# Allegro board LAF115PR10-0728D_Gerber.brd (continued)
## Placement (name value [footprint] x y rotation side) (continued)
PRS23  100K_0402_5%  [R_0402]  51.24 119.59 90 top
PRS25  1M_0402_1%  [R_0402]  57.31 128.38 90 top
PRS26  1M_0402_1%  [R_0402]  65.72 120.83 90 top
PRS27  1M_0402_1%  [R_0402]  65.75 123.43 270 top
PRS28  10K_0402_1%  [R_0402]  62.32 122.56 90 top
PRS29  100K_0402_1%  [R_0402]  64.94 124.26 0 top
PRS30  100K_0402_1%  [R_0402]  64.25 116.98 180 top
PRS32  0_0402_5%  [R_0402]  45.7 117.91 180 top
PRS33  0_0402_5%  [R_0402]  52.07 122.84 270 top
PRS34  10K_0402_1%  [R_0402]  62.26 124.44 90 top
PRS35  0_0402_5%  [R_0402]  66.39 127.14 270 top
PRS36  300K_0402_1%  [R_0402]  53.95 135.07 270 top
PRS37  100K_0402_5%  [R_0402]  52.82 131 180 top
PRS38  0_0402_5%  [R_0402]  49.48 127.71 0 top
PRS39  0_0402_5%  [R_0402]  48.15 118.82 0 top
PRS40  0_0402_5%  [R_0402]  49.81 118.82 0 top
PRS41  0_0402_5%  [R_0402]  52.84 122.84 270 top
PRS42  0_0402_5%  [R_0402]  51.24 122.97 90 top
PRS43  0_0402_5%  [R_0402]  53.64 124.28 180 top
PRS44  0_0402_5%  [R_0402]  54.44 124.28 0 top
PRS45  0_0402_5%  [R_0402]  41.72 125.97 90 top
PRV01  0_0603_5%  [R0603_0OHM]  77.12 133.79 0 top
PRV02  32.4K_0402_1%  [R_0402]  73.19 133.73 90 top
PRV03  10K_0402_1%  [R_0402]  67.22 120.79 0 top
PRV04  10K_0402_1%  [R_0402]  73.96 133.73 90 top
PRV05  10K_0402_1%  [R_0402]  74.74 133.73 90 top
PRV06  4.7_1206_5%  [R_1206]  90.92 134.44 270 top
PRV07  3.65K_0603_1%  [R_0603]  66.96 121.79 0 top
PRV08  1_0402_1%  [R_0402]  66.89 123.71 270 top
PRV09  100K_0402_1%  [R_0402]  69.95 132.33 180 top
PRV10  100K_0402_1%  [R_0402]  71.79 133.71 90 top
PRV12  0_0402_5%  [R_0402]  67.84 131.06 0 top
PRV13  1_0603_5%  [R_0603]  79.6 131.06 270 top
PRV14  0_0402_5%  [R_0402]  67.84 130.23 0 top
PRV15  0_0402_5%  [R0402_0OHM]  68.73 129.34 0 top
PRV16  133K_0402_1%  [R_0402]  67.98 128.53 270 top
PRV17  100K_0402_1%  [R_0402]  79.49 125.85 180 top
PRV18  150K_0402_1%  [R_0402]  67.15 125.71 90 top
PRV19  13.3K_0402_1%  [R_0402]  67.98 126.63 270 top
PRV20  0_0402_5%  [R0402_0OHM]  78.59 125.05 0 top
PRV21  0_0603_5%  [R0603_0OHM]  78.39 127.25 0 top
PRV22  10K_0402_1%  [R_0402]  70.25 120.25 270 top
PRV23  4.7_1206_5%  [R_1206]  90.97 125.45 90 top
PRV24  3.65K_0603_1%  [R_0603]  68.08 118.46 90 top
PRV25  1_0402_1%  [R_0402]  71.92 121.84 90 top
PRV26  301_0402_1%  [R_0402]  73.76 124.53 270 top
PRV27  121K_0402_1%  [R_0402]  77.05 122.61 0 top
PRV28  2.61K_0402_1%  [R_0402]  70.9 122.03 270 top
PRV29  1.37K_0402_1%  [R_0402]  74.58 124.53 270 top
PRV30  11K_0402_1%  [R_0402]  70.07 123.49 90 top
PRV31  22.1K_0402_1%  [R_0402]  74.52 121.99 270 top
PRV32  2K_0402_1%  [R_0402]  73.69 121.99 270 top
PRV33  665_0402_1%  [R_0402]  72.68 123.62 90 top
PRV34  0_0402_5%  [R0402_0OHM]  76.31 123.57 180 top
PRV35  100_0402_1%  [R_0402]  71.85 123.62 90 top
PRV36  0_0402_5%  [R0402_0OHM]  77.57 124.44 90 top
PRW01  0_0402_5%  [R0402_0OHM]  140.06 112.25 270 bottom
PRW02  1M_0402_1%  [R_0402]  139.28 111.34 90 bottom
PRW03  0_0402_5%  [R_0402]  147.39 111.15 180 top
PRW04  0_0402_5%  [R_0402]  145.14 111.45 90 bottom
PRW05  100K_0402_5%  [R_0402]  140.88 112.25 270 bottom
PRW06  10_0603_5%  [R_0603]  144.81 108.13 0 top
PRW07  4.7_1206_5%  [R_1206]  147.78 109.77 0 top
PRW09  39.2K_0402_1%  [R_0402]  143.46 111.49 90 bottom
PRW10  31.6K_0402_1%  [R_0402]  142.67 112.24 180 bottom
PRW11  2.2_0402_1%  [R_0402]  144.82 110.75 225 top
PRW13  1K_0402_1%  [R_0402]  146.04 114.4 225 bottom
PRZ01  1.5K_0402_1%  [R_0402]  182.16 55.82 90 top
PRZ03  0_0402_5%  [R0402_0OHM]  182.36 53.61 180 top
PRZ04  1.78K_0402_1%  [R_0402]  181.21 52.72 180 bottom
PRZ05  18.2K_0402_1%  [R_0402]  179.02 55.4 180 top
PRZ06  10_0402_5%  [R_0402]  183.14 56.17 180 bottom
PRZ07  0_0402_5%  [R0402_0OHM]  182.36 54.5 180 top
PRZ08  1K_0402_1%  [R_0402]  181.26 54.47 180 bottom
PRZ10  12K_0402_1%  [R_0402]  180.7 59.08 270 top
PRZ11  20K_0402_1%  [R_0402]  178.11 54.52 0 top
PRZ13  7.5K_0603_1%  [R_0603]  154.03 58.95 270 top
PRZ14  0_0402_5%  [R0402_0OHM]  182.15 51.71 180 bottom
PRZ15  54.9K_0402_1%  [R_0402]  179.02 57.13 180 top
PRZ16  10K_0402_1%  [R_0402]  180.76 58.52 180 bottom
PRZ18  0_0402_5%  [R0402_0OHM]  181.26 50.02 90 bottom
PRZ19  1K_0402_1%  [R_0402]  180.38 51.5 90 top
PRZ20  49.9_0402_1%  [R_0402]  179.57 49.56 270 bottom
PRZ21  619_0402_1%  [R_0402]  179.58 50.44 180 bottom
PRZ22  0_0402_5%  [R0402_0OHM]  179.84 59.3 0 bottom
PRZ23  24.9K_0402_1%  [R_0402]  177.45 52.32 90 top
PRZ24  4.75K_0402_1%  [R_0402]  178.5 50.22 270 top
PRZ25  66.5K_0603_1%  [R_0603]  176.33 48.98 90 top
PRZ26  165K_0402_1%  [R_0402]  174.87 48.68 0 bottom
PRZ27  75K_0402_1%  [R_0402]  176.52 48.68 0 bottom
PRZ28  9.76K_0402_1%  [R_0402]  177.17 49.56 90 bottom
PRZ29  66.5K_0603_1%  [R_0603]  175.12 48.98 90 top
PRZ30  10_0402_1%  [R_0402]  159.79 72.77 0 bottom
PRZ31  10_0402_1%  [R_0402]  160.99 71.64 0 bottom
PRZ32  10K_0402_1%  [R_0402]  173.69 49.64 180 top
PRZ33  10K_0402_1%  [R_0402]  174.39 49.57 180 bottom
PRZ34  0_0402_5%  [R0402_0OHM]  171.79 52.02 0 top
PRZ35  1K_0402_1%  [R_0402]  170.68 50.52 0 bottom
PRZ36  61.9K_0402_1%  [R_0402]  171.79 52.91 0 top
PRZ37  2.15K_0402_1%  [R_0402]  171.96 47.34 90 top
PRZ38  2.15K_0402_1%  [R_0402]  173.61 47.34 90 top
PRZ39  1K_0402_1%  [R_0402]  172.79 47.34 90 top
PRZ40  45.3_0402_1%  [R_0402]  178.06 61.12 90 top
PRZ41  110_0402_1%  [R_0402]  177.17 61.12 90 top
PRZ42  100_0402_1%  [R_0402]  176.28 61.12 90 top
PRZ43  110_0402_1%  [R_0402]  175.39 61.12 90 top
PRZ44  7.5K_0603_1%  [R_0603]  152.56 94.61 90 top
PRZ45  12K_0402_1%  [R_0402]  174.27 63.04 270 bottom
PRZ46  49.9_0402_1%  [R_0402]  177.49 60.7 90 bottom
PRZ47  0_0402_5%  [R0402_0OHM]  176.71 61.13 90 bottom
PRZ48  10_0402_1%  [R_0402]  175.92 61.13 90 bottom
PRZ49  100_0402_1%  [R_0402]  175.15 61.13 90 bottom
PRZ50  97.6K_0402_1%  [R_0402]  176.47 59.41 270 top
PRZ51  10_0402_5%  [R_0402]  173.5 63.03 270 bottom
PRZ52  1K_0402_1%  [R_0402]  169.27 58.93 90 bottom
PRZ53  0_0402_5%  [R0402_0OHM]  171.39 62.03 90 top
PRZ55  2K_0402_1%  [R_0402]  171.81 63.04 270 bottom
PRZ56  52.3K_0402_1%  [R_0402]  173.89 59.41 270 top
PRZ57  2_0402_1%  [R_0402]  169.32 51.96 0 bottom
PRZ58  4.32K_0402_1%  [R_0402]  169.8 60.76 270 top
PRZ59  0_0402_5%  [R0402_0OHM]  169.8 62.92 270 top
PRZ60  24K_0402_1%  [R_0402]  171.79 53.8 0 top
PRZ61  3.65K_0402_1%  [R_0402]  168.98 60.76 270 top
PRZ63  0_0402_5%  [R0402_0OHM]  170.18 57.14 270 bottom
PRZ64  24K_0402_1%  [R_0402]  170.16 54.12 180 bottom
PRZ65  61.9K_0402_1%  [R_0402]  169.29 56.23 90 bottom
PRZ66  51.1K_0402_1%  [R_0402]  171.79 54.69 0 top
PRZ67  97.6K_0402_1%  [R_0402]  171.79 55.58 0 top
PRZ68  19.1K_0402_1%  [R_0402]  171.79 56.47 0 top
PRZ69  35.7K_0402_1%  [R_0402]  171.79 57.36 0 top
PU1  -  [RT9069-33GB_SOT23-5]  83.84 144.17 180 top
PU2  -  [SN74AHC1G08DCKR_SC70-5]  95.96 147.73 90 top
PU301  -  [SY8286BRAC_QFN20_3X3]  20.79 41.49 90 bottom
PU501  SY8180CRAC_QFN20_3X3  [SY8288CRAC_QFN20_3X3]  24.66 98.72 270 bottom
PU1801  -  [RT8061AZQW_WDFN10_3X3]  167.06 43.42 90 bottom
PU2501  -  [RT9059GSP_SO8]  71.51 110.42 90 top
PUA01  -  [NCP81253MNTBG_DFN8_2X2]  166.06 59.69 270 bottom
PUB01  -  [ISL9538HRTZ-T_TQFN32_4X4]  205.97 43.79 90 bottom
PUB02  SN74AHC1G08DCKR_SC70-5  [TC7SH08FU_SSOP5]  165.07 34.08 270 top
PUG01  -  [NCP302045MNTXG_PQFN33_5X5]  157.84 95.25 0 bottom
PUH01  -  [RT6228AGQUF_UQFN12_3X3]  162.56 49.8 90 bottom
PUI01  -  [NCP302045MNTXG_PQFN33_5X5]  162.02 70.01 0 bottom
PUI02  -  [NCP302045MNTXG_PQFN33_5X5]  166.87 87.52 270 bottom
PUM01  -  [RT8207PGQW_WQFN20_3X3]  37.65 30.36 180 top
PUS01  AS393MMTR-G1_MSOP8  [LM393DGKR_VSSOP8]  48.98 115.91 0 top
PUS02  -  [SN74AHC1G08DCKR_SC70-5]  59.69 125.79 90 top
PUS03  -  [TC7SH32FU_SSOP5]  52.17 126.54 270 top
PUS04  RT9058-33GX SOT-89 3P  [AP2204R-5P0TRG1_SOT89-3]  77.28 144.12 0 top
PUV01  -  [ISL62771HRTZ-T_TQFN40_5X5]  71.63 131.5 0 top
PUW01  -  [RT6226AGQUF_UQFN12_3X3]  144.7 109.12 180 bottom
PUZ01  -  [NCP81218MNTXG_QFN48_6X6]  177.63 52.85 90 bottom
Q1  -  [2N7002K_SOT23-3]  44.04 52.46 180 top
Q4  -  [L2N7002WT1G_SC-70-3]  59.98 33.43 270 top
Q6  -  [LN2306LT1G_SOT23-3]  46.38 48.11 270 top
Q7  -  [DDTA144VCA-7-F_SOT23-3]  48.1 44.11 90 top
Q8  -  [LN2306LT1G_SOT23-3]  82.16 47.8 270 top
Q9  -  [LN2306LT1G_SOT23-3]  124.58 26.06 0 top
Q10  -  [DMN66D0LDW-7_SOT363-6]  119.04 28.44 270 top
Q11  -  [DMN66D0LDW-7_SOT363-6]  182.26 65.13 0 top
Q12  NTK3139PT1G_SOT723-3  [2N7002K_SOT23-3]  131.29 27.39 0 top
Q13  -  [2N7002K_SOT23-3]  135.29 29.36 180 top
Q14  -  [LMBT3904LT1G_SOT23-3]  84.83 118.42 270 bottom
Q15  LP2301ALT1G 1P SOT-23-3  [SI2301CDS-T1-GE3_SOT23-3]  60.24 27.21 0 top
Q17  -  [DMN66D0LDW-7_SOT363-6]  46.61 95.85 90 top
Q18  -  [DDTA144VCA-7-F_SOT23-3]  48.36 94.47 270 top
Q19  -  [DDTA144VCA-7-F_SOT23-3]  48.36 98.47 270 top
Q20  -  [DDTA144VCA-7-F_SOT23-3]  50.81 37.07 180 top
Q21  -  [LN2306LT1G_SOT23-3]  55.48 32.09 0 top
Q22  -  [LN2306LT1G_SOT23-3]  48.3 102.4 270 top
Q23  -  [LP2301ALT1G_SOT23-3]  64.22 30.25 180 top
Q24  -  [L2N7002WT1G_SC-70-3]  65.95 32.21 180 top
Q25  -  [DMN66D0LDW-7_SOT363-6]  51.65 107.2 0 top
QA1  -  [LN2306LT1G_SOT23-3]  36.7 20.39 180 top
QC1  -  [DMN66D0LDW-7_SOT363-6]  100.09 36.74 0 bottom
QC2  -  [2N7002K_SOT23-3]  99 45.23 0 top
QI1  -  [2N7002K_SOT23-3]  27.54 92.85 90 top
QI2  -  [DMN66D0LDW-7_SOT363-6]  26.04 88.04 90 bottom
QI3  2N7002KW_SOT323-3  [DMN65D8LW-7_SOT323-3]  26.36 114.07 90 top
QS1  -  [DMN66D0LDW-7_SOT363-6]  195.93 37.05 180 top
QT3  -  [2N7002K_SOT23-3]  21.06 130.79 270 top
QT4  -  [LN2306LT1G_SOT23-3]  26.46 117.77 270 top
QT5  -  [LN2306LT1G_SOT23-3]  33.28 130.51 270 top
QV1  DMN66D0LDW-7 2N SOT363-6  [2N7002KDWH_SOT363-6]  123.66 120.85 0 top
R1  1K_0402_5%  [R_0402]  41.82 48.08 270 top
R2  10M_0402_5%  [R_0402]  42.64 47.77 90 top
R3  0_0805_5%  [R_0805]  212.35 50.33 270 top
R4  0_0603_5%  [R_0603]  217.17 25.25 90 top
R5  10K_0402_5%  [R_0402]  210.05 55.35 270 top
R6  0_0402_5%  [R_0402]  210.05 53.7 270 top
R7  0_0603_5%  [R_0603]  216.03 29.06 270 top
R8  0_0402_5%  [R0402_0OHM]  178.3 70.9 45 top
R9  0_0402_5%  [R_0402]  177.73 71.47 45 top
R10  100K_0402_5%  [R_0402]  166.61 31.81 180 top
R11  0_0603_5%  [R_0603]  215.58 33.76 90 top
R12  0_0603_5%  [R_0603]  216.92 37.57 180 bottom
R13  0_0603_5%  [R_0603]  213.39 40.08 180 top
R16  0_0603_5%  [R_0603]  212.33 47.6 270 top
R17  0_0402_5%  [R_0402-NPM]  214.33 43.86 0 top
R18  0_0402_5%  [R_0402-NPM]  214.33 44.62 0 top
R19  33_0402_5%  [R_0402]  214.09 41.43 90 top
R20  0_0402_5%  [R_0402]  207.98 39.98 0 top
R21  0_0402_5%  [R_0402]  207.98 40.75 0 top
R22  100_0402_5%  [R_0402]  219.92 66.95 270 top
R23  10K_0402_5%  [R_0402]  55.51 81.77 180 top
R24  100K_0402_5%  [R_0402]  50.15 47.45 90 top
R25  1K_0402_5%  [R_0402]  50.17 44.76 90 top
R26  51K_0402_5%  [R_0402]  88.16 35.99 0 bottom
R27  100K_0402_5%  [R_0402]  87.38 35.95 90 bottom
R28  18.7K_0402_1%  [R_0402]  174.96 64.4 315 bottom
R29  2K_0402_1%  [R_0402]  178.43 61.14 315 bottom
R30  10K_0402_5%  [R_0402]  208.61 37 180 top
R31  4.7K_0402_5%  [R_0402]  115.88 27.57 180 top
R32  4.7K_0402_5%  [R_0402]  118.09 26.12 270 top
R33  4.7K_0402_5%  [R_0402]  121.95 27.61 270 top
R34  4.7K_0402_5%  [R_0402]  118.57 30.05 45 top
R35  0_0402_5%  [R_0402]  128.99 31.28 0 top
R36  0_0603_5%  [R_0603]  129.78 25.4 0 top
R37  100_0603_5%  [R_0603]  135.29 25.38 180 top
R38  20K_0402_1%  [R_0402]  133.37 31.25 180 top
R39  10K_0402_5%  [R_0402]  122.21 25.07 90 top
R40  4.7K_0402_5%  [R_0402]  127.91 26.67 270 top
R41  100K_0402_5%  [R_0402]  117.98 33.36 0 bottom
R42  24.9K_0402_1%  [R_0402]  109.5 107.62 90 top
R43  7.15K_0402_1%  [R_0402]  111.3 107.71 90 top
R45  0_0402_5%  [R_0402]  122.94 43.21 90 top
R46  2.2K_0402_5%  [R_0402]  121.95 29.24 270 top
R47  2.2K_0402_5%  [R_0402]  116.99 26.96 90 top
R48  2.2K_0402_5%  [R_0402]  183.05 64.11 180 top
R49  2.2K_0402_5%  [R_0402]  182.77 68.05 0 top
R50  10K_0402_5%  [R_0402]  180.37 69.4 45 top
R53  100K_0402_5%  [R_0402]  53.17 35.75 270 top
R57  10K_0402_5%  [R_0402]  209.71 50.05 180 top
R65  499K_0402_1%  [R_0402]  61.03 31.54 0 top
R66  100K_0402_5%  [R_0402]  59.67 31.55 180 top
R67  49.9K_0402_1%  [R_0402]  61.95 32.43 180 top
R68  200_0402_5%  [R_0402]  16.18 131.61 0 bottom
R69  200_0402_5%  [R_0402]  16.18 132.38 0 bottom
R70  100K_0402_5%  [R_0402]  219.11 66.05 90 top
R71  0_0402_5%  [R_0402]  43.79 95.55 90 top
R72  100K_0402_5%  [R_0402]  223.13 33.61 180 bottom
R73  10K_0402_5%  [R_0402]  64.25 34.35 270 top
R77  0_0402_5%  [R_0402]  39.9 24.27 0 bottom
R78  1M_0402_5%  [R_0402]  69 30.74 270 top
R79  100K_0402_5%  [R_0402]  67.51 28.29 180 top
R80  0_0402_5%  [R_0402]  214.65 47.71 0 top
R81  0_0402_5%  [R_0402]  49.46 104.75 0 top
R82  100K_0402_5%  [R_0402]  53.13 110.17 180 top
R83  100K_0402_5%  [R_0402]  53.97 110.17 270 top
R84  0_0402_5%  [R_0402]  62.63 26.32 0 top
R85  0_0603_5%  [R_0603]  215.58 48.8 180 top
R86  0_0402_5%  [R_0402]  219.12 27.34 270 top
R87  0_0402_5%  [R_0402]  220.07 26.42 90 top
RA1  0_0805_5%  [R0805_0OHM]  31.8 3.23 180 top
RA2  0_0402_5%  [R0402_0OHM]  33.71 21.2 180 top
RA3  100K_0402_5%  [R_0402]  31.1 17.86 0 top
RA4  0_0603_5%  [R0603_0OHM]  31.82 19.06 180 top
RA5  0_0402_5%  [R0402_0OHM]  22.04 6.7 90 top
RA6  0_0402_5%  [R0402_0OHM]  21.28 6.05 180 top
RA7  33_0402_5%  [R_0402]  32.57 14.79 180 top
RA8  10K_0402_5%  [R_0402]  30.88 8.04 180 top
RA9  0_0402_5%  [R_0402]  38.53 15.47 0 top
RA10  200K_0402_1%  [R_0402]  30.37 17.86 180 top
RA11  0_0402_5%  [R_0402]  29.22 22.06 0 top
RA12  0_0402_5%  [R_0402]  29.22 22.84 0 top
RA13  BLM15PD800SN1D_2P  [MURAT_BLM15PD600SN1D_2P]  26.79 3.92 180 top
RA14  BLM15PD800SN1D_2P  [MURAT_BLM15PD600SN1D_2P]  26.79 2.77 180 top
RA15  BLM15PD800SN1D_2P  [MURAT_BLM15PD600SN1D_2P]  26.2 7.65 270 top
RA16  BLM15PD800SN1D_2P  [MURAT_BLM15PD600SN1D_2P]  27.34 7.65 270 top
RA17  0_0402_5%  [R0402_0OHM]  12.76 6.1 270 top
RA18  0_0402_5%  [R0402_0OHM]  11.97 6.1 270 top
RA22  0_0805_5%  [R0805_0OHM]  24.83 23.59 90 top
RA23  1K_0402_5%  [R_0402]  30.13 21.28 180 top
RA24  10K_0402_5%  [R_0402]  29.21 20.51 0 top
RA25  2.2K_0402_5%  [R_0402]  27.75 19.64 180 top
RA26  2.2K_0402_5%  [R_0402]  25.21 18.85 0 top
RA27  10_0402_1%  [R_0402]  20.35 12.67 180 top
RA28  1K_0402_5%  [R_0402]  21.84 19.96 90 top
RA29  4.7K_0402_5%  [R_0402]  20.35 13.44 180 top
RA30  10K_0402_5%  [R_0402]  16.38 11.46 90 bottom
RA31  10_0402_1%  [R_0402]  16.34 12.3 90 top
RA32  1K_0402_5%  [R_0402]  22.61 19.96 90 top
RA33  4.7K_0402_5%  [R_0402]  18.89 14.46 180 top
RA34  10K_0402_5%  [R_0402]  16.38 14.15 270 bottom
RA35  BLM15PX330SN1D_2P  [MURAT_BLM15PX330SN1D_2P]  26.93 20.74 90 top
RA36  0_0402_5%  [R0402_0OHM]  18.72 12.15 180 top
RA37  0_0402_5%  [R0402_0OHM]  17.26 14 180 top
RA38  BLM15PX330SN1D_2P  [MURAT_BLM15PX330SN1D_2P]  26.02 20.74 90 top
RA39  0_0603_5%  [R0603_0OHM]  16.72 19.27 270 top
RA40  0_0402_5%  [R0402_0OHM]  15.71 18.17 90 top
RA41  100K_0402_5%  [R_0402]  19.47 17.74 270 top
RA42  33_0402_5%  [R_0402]  32.62 10.35 180 top
RA43  33_0402_5%  [R_0402]  34.49 15.41 180 top
RC1  2.2K_0402_5%  [R_0402]  131.89 39.54 270 bottom
RC2  2.2K_0402_5%  [R_0402]  131.09 39.52 270 bottom
RC3  10K_0402_5%  [R_0402]  141.19 48.4 270 bottom
RC4  24.9_0402_1%  [R_0402]  144.28 82.51 270 top
RC5  100K_0402_5%  [R_0402]  128.86 52.23 90 top
RC6  100K_0402_5%  [R_0402]  128.56 54.87 90 top
RC7  100_0402_1%  [R_0402]  133.99 55.98 180 top
RC8  200_0402_1%  [R_0402]  115.72 46.26 270 bottom
RC9  100K_0402_5%  [R_0402]  105.48 104.04 270 top
RC10  121_0402_1%  [R_0402]  104.21 60.49 180 top
RC11  80.6_0402_1%  [R_0402]  105.09 62.21 225 top
RC12  100_0402_1%  [R_0402]  106.19 60.49 180 top
RC14  10K_0402_5%  [R_0402]  104.52 51.94 0 top
RC15  22_0402_5%  [R_0402]  106.19 54.97 180 top
RC17  0_0603_5%  [R0603_0OHM]  130.37 40.49 180 bottom
RC18  4.7K_0402_5%  [R_0402]  114.94 45.34 90 bottom
RC19  1K_0402_5%  [R_0402]  110.42 45.27 90 bottom
RC20  1K_0402_5%  [R_0402]  114.05 46.26 270 bottom
RC21  33_0402_5%  [R_0402]  109.53 45.62 90 bottom
RC22  1M_0402_1%  [R_0402]  144.4 45.33 270 bottom
RC23  33_0402_5%  [R_0402]  141.99 73.24 90 bottom
RC24  33_0402_5%  [R_0402]  141.99 71.47 90 bottom
RC25  33_0402_5%  [R_0402]  142.75 44.53 0 bottom
RC26  33_0402_5%  [R_0402]  142.75 45.29 0 bottom
RC27  2.2K_0402_5%  [R_0402]  100.35 33.89 0 bottom
RC28  2.2K_0402_5%  [R_0402]  103.63 37.55 180 bottom
RC29  1K_0402_5%  [R_0402]  128.83 41.51 0 bottom
RC30  1K_0402_5%  [R_0402]  128.83 42.4 0 bottom
RC31  1K_0402_5%  [R_0402]  130.91 46.4 270 bottom
RC32  1K_0402_5%  [R_0402]  131.73 46.46 270 bottom
RC33  1K_0402_5%  [R_0402]  127.54 53.96 270 top
RC34  1K_0402_5%  [R_0402]  129.26 46.4 270 bottom
RC35  10K_0402_5%  [R_0402]  144.34 39.25 180 bottom
RC36  10K_0402_5%  [R_0402]  123.43 44.43 0 bottom
RC37  2.2K_0402_5%  [R_0402]  127.49 57 0 top
RC38  4.7K_0402_5%  [R_0402]  130.09 46.4 270 bottom
RC39  150K_0402_5%  [R_0402]  121.29 46.07 180 top
RC40  1K_0402_1%  [R_0402]  106.17 39.21 90 bottom
RC41  1K_0402_1%  [R_0402]  113.03 45.8 180 bottom
RC42  10K_0402_5%  [R_0402]  125.49 45.55 90 bottom
RC44  4.7K_0402_5%  [R_0402]  110.82 51.71 90 bottom
RC45  10K_0402_5%  [R_0402]  122.22 46.07 0 top
RC46  10K_0402_5%  [R_0402]  131.96 42.2 180 bottom
RC47  10K_0402_5%  [R_0402]  122.3 46.41 270 bottom
RC48  10K_0402_5%  [R_0402]  143.04 37.42 270 bottom
RC49  10K_0402_5%  [R_0402]  143.97 38.27 180 bottom
RC50  150K_0402_5%  [R_0402]  143.93 36.5 90 bottom
RC51  10K_0402_5%  [R_0402]  123.43 42.78 0 bottom
RC52  10K_0402_5%  [R_0402]  124.35 43.6 180 bottom
RC53  10K_0402_5%  [R_0402]  120.65 45.5 90 bottom
RC54  10K_0402_5%  [R_0402]  122.18 42.7 90 bottom
RC55  10K_0402_5%  [R_0402]  126.25 45.55 90 bottom
RC56  10K_0402_5%  [R_0402]  127.03 46.47 270 bottom
RC57  10K_0402_5%  [R_0402]  125.59 44.63 270 bottom
RC58  10K_0402_5%  [R_0402]  126.48 43.71 90 bottom
RC59  10K_0402_5%  [R_0402]  104.57 41.38 0 top
RC60  10K_0402_5%  [R_0402]  105.36 40.55 180 top
RC61  10K_0402_5%  [R_0402]  129.74 43.22 180 bottom
RC62  10K_0402_5%  [R_0402]  128.83 44.05 0 bottom
RC63  10K_0402_5%  [R_0402]  145.81 47.98 180 bottom
RC64  10K_0402_5%  [R_0402]  144.9 48.75 0 bottom
RC65  100_0402_1%  [R_0402]  133.08 52.41 0 top
RC66  113_0402_1%  [R_0402]  126.4 51.95 270 top
RC67  1K_0402_5%  [R_0402]  122.23 50.58 90 top
RC68  1K_0402_5%  [R_0402]  121.48 46.41 270 bottom
RC69  10K_0402_5%  [R_0402]  143.52 40.06 0 bottom
RC71  10K_0402_5%  [R_0402]  104.5 52.74 0 top
RC72  10K_0402_5%  [R_0402]  105.27 46.74 0 top
RC73  10K_0402_5%  [R_0402]  105.27 45.97 0 top
RC74  0_0402_5%  [R_0402]  100.78 39.21 90 bottom
RC75  0_0402_5%  [R_0402]  101.54 39.21 90 bottom
RC76  2.71K_0402_1%  [R_0402]  142.88 76.8 90 bottom
RC77  20K_0402_5%  [R_0402]  99.93 43.44 270 top
RC78  20K_0402_5%  [R_0402]  100.75 43.44 270 top
RC80  1M_0402_1%  [R_0402]  142.88 73.24 90 bottom
RC82  10M_0402_5%  [R_0402]  104.28 50.23 0 top
RC86  10K_0402_5%  [R_0402]  139.78 48 90 bottom
RC87  100K_0402_5%  [R_0402]  98.45 40.12 270 bottom
RC88  10K_0402_5%  [R_0402]  105.36 39.75 180 top
RC89  8.2K_0402_5%  [R_0402]  106.19 54.02 180 top
RC90  10K_0402_5%  [R_0402]  103.49 54.02 0 top
RC91  1M_0402_5%  [R_0402]  99.1 43.44 270 top
RC92  10K_0402_5%  [R_0402]  121.4 51.48 270 top
RC93  100K_0402_5%  [R_0402]  105.27 56.55 0 top
RC94  10K_0402_5%  [R_0402]  105.26 58.71 0 top
RC95  1K_0402_5%  [R_0402]  140.66 91.86 180 bottom
RC96  60.4_0402_1%  [R_0402]  140.66 87.16 180 bottom
RC97  0_0402_5%  [R0402_0OHM]  108.88 58.9 0 bottom
RC99  0_0402_5%  [R0402_0OHM]  105.27 55.73 0 top
RC102  1M_0402_5%  [R_0402]  100.63 28.43 180 bottom
RC103  10K_0402_1%  [R_0402]  147.02 87.93 180 bottom
RC104  1K_0402_5%  [R_0402]  142.22 87.79 0 bottom
RC105  10K_0402_5%  [R_0402]  148.35 91.86 180 bottom
RC106  0_0402_5%  [R0402_0OHM]  148.35 92.62 180 bottom
RC107  0_0402_5%  [R0402_0OHM]  147.44 93.45 0 bottom
RC108  0_0402_5%  [R_0402]  106.2 42.51 90 top
RC109  100K_0402_5%  [R_0402]  106.2 45.2 270 top
RC110  1K_0402_5%  [R_0402]  102.74 42.45 90 top
RC111  49.9_0402_1%  [R_0402]  143.26 84.24 180 bottom
RC112  1K_0402_5%  [R_0402]  143.26 85.13 180 bottom
RC113  1K_0402_5%  [R_0402]  128.65 96.38 270 top
RC114  10K_0402_5%  [R_0402]  109.53 49.7 0 bottom
RC115  10K_0402_5%  [R_0402]  108.75 49.73 270 bottom
RC116  10K_0402_5%  [R_0402]  141.46 51.28 0 bottom
RC117  499_0402_1%  [R_0402]  129.61 95.47 90 top
RC118  0_0402_5%  [R_0402]  109.53 48.87 0 bottom
RC119  49.9_0402_1%  [R_0402]  106.19 57.73 180 top
RC120  49.9_0402_1%  [R_0402]  104.21 59.6 180 top
RC121  49.9_0402_1%  [R_0402]  131.69 87.08 90 top
RC122  49.9_0402_1%  [R_0402]  131.69 86.22 270 top
RC123  33_0402_5%  [R_0402]  98.99 50.55 0 top
RC124  33_0402_5%  [R_0402]  108.5 60.39 0 bottom
RC125  33_0402_5%  [R_0402]  102.38 46.02 180 top
RC126  1K_0402_5%  [R_0402]  102.37 47.63 180 top
RC127  33_0402_5%  [R_0402]  101.57 50.54 180 top
RC128  8.2K_0402_5%  [R_0402]  103.56 46.59 0 top
RC129  4.7K_0402_5%  [R_0402]  102.37 46.84 180 top
RC130  200_0402_1%  [R_0402]  123.9 53.73 90 top
RC131  10K_0402_1%  [R_0402]  141.63 89.48 180 bottom
RC132  10K_0402_1%  [R_0402]  140.67 93.89 180 bottom
RC133  10K_0402_1%  [R_0402]  139.74 90.97 0 bottom
RC134  49.9_0402_1%  [R_0402]  133.49 83.98 180 top
RC136  10K_0402_1%  [R_0402]  133.53 91.08 90 top
RC137  0_0402_5%  [R_0402]  128.89 46.34 0 top
RC138  100K_0402_5%  [R_0402]  131.45 96.38 270 top
RC139  1K_0402_5%  [R_0402]  106.94 40.12 270 bottom
RC140  51_0402_5%  [R_0402]  127.76 95.47 90 top
RC141  51_0402_5%  [R_0402]  126.87 95.47 90 top
RC142  51_0402_5%  [R_0402]  125.99 95.47 90 top
RC143  1K_0402_5%  [R_0402]  129.16 50.45 90 top
RC144  0_0402_5%  [R_0402]  124.27 94.1 270 top
RC145  0_0402_5%  [R_0402]  105.7 37.4 180 top
RC146  51_0402_1%  [R_0402]  125.1 95.47 90 top
RC147  51_0402_5%  [R_0402]  139.81 83.33 0 bottom
RC148  1K_0402_5%  [R_0402]  99.21 40.12 270 bottom
RC149  0_0603_5%  [R_0603]  127.89 48.87 0 top
RC150  100_0402_1%  [R_0402]  141.83 67.1 90 bottom
RC151  100_0402_1%  [R_0402]  141.83 68.75 90 bottom
RC152  56_0402_1%  [R_0402]  143.26 86.02 180 bottom
RC153  220_0402_5%  [R_0402]  139.75 85.89 0 bottom
RC154  100_0402_1%  [R_0402]  143.13 86.9 180 bottom
RC155  100_0402_1%  [R_0402]  131.78 92.62 180 top
RC156  100_0402_1%  [R_0402]  130.56 92.81 90 bottom
RC157  0_0402_5%  [R_0402]  131.43 77.57 90 top
RC159  100_0402_1%  [R_0402]  146.59 57.54 90 top
RC160  100_0402_1%  [R_0402]  144.44 61.14 0 top
RC161  0_0603_5%  [R_0603]  145.86 45.25 270 top
RC162  0_0603_5%  [R_0603]  144.59 45.25 270 top
RC163  0_0402_5%  [R_0402]  102.95 39.59 180 top
RC164  10K_0402_5%  [R_0402]  96.58 47.04 90 top
RC169  0_0603_5%  [R0603_0OHM]  133.61 48.28 180 top
RC170  0_0603_5%  [R0603_0OHM]  144.54 55.03 270 top
RC171  0_0603_5%  [R0603_0OHM]  130.81 59.66 90 top
RC173  0_0603_5%  [R0603_0OHM]  126.68 60.68 0 top
RC174  0_0603_5%  [R0603_0OHM]  144.59 47.03 90 top
RC175  0_0402_5%  [R_0402]  124.27 96.38 270 top
RC176  15_0402_5%  [R_0402]  111.34 46.19 270 bottom
RC177  15_0402_5%  [R_0402]  121.27 37.82 0 bottom
RC178  15_0402_5%  [R_0402]  122.19 38.64 180 bottom
RC179  15_0402_5%  [R_0402]  122.18 39.43 180 bottom
RC180  15_0402_5%  [R_0402]  122.19 36.94 180 bottom
RC181  10K_0402_5%  [R_0402]  104.45 38.17 0 top
RC182  10K_0402_5%  [R_0402]  105.36 38.93 180 top
RC188  10K_0402_5%  [R_0402]  105.41 39.21 90 bottom
RC194  10K_0402_5%  [R_0402]  192.2 63.93 90 top
RC199  0_0402_5%  [R_0402]  100.05 40.86 180 top
RC200  10K_0402_5%  [R_0402]  128.8 43.39 0 top
RC201  0_0402_5%  [R_0402]  116.45 53.92 0 top
RC202  0_0402_5%  [R_0402]  113 95.36 180 bottom
RC203  0_0402_5%  [R_0402]  118.5 39.2 270 bottom
RC205  10K_0402_5%  [R_0402]  127.86 46.44 270 bottom
RC206  10K_0402_5%  [R_0402]  132.32 37.52 180 bottom
RC207  10K_0402_5%  [R_0402]  215.75 32.28 225 top
RC208  10K_0402_5%  [R_0402]  214.16 59.19 270 top
RC209  10K_0402_5%  [R_0402]  182.24 37.52 90 bottom
RC211  100K_0402_5%  [R_0402]  102.68 54.01 90 top
RC212  2.2K_0402_5%  [R_0402]  142.81 34.98 0 top
RC213  10K_0402_5%  [R_0402]  118.75 51.4 225 top
RC214  10K_0402_5%  [R_0402]  120.57 58.01 90 top
RC223  0_0402_5%  [R_0402]  42.63 90.08 180 top
RC224  10K_0402_5%  [R_0402]  47.53 100.95 270 top
RC225  10K_0402_5%  [R_0402]  44.2 101.02 180 top
RC226  10K_0402_5%  [R_0402]  42.82 98.53 180 top
RC227  1K_0402_5%  [R_0402]  130.36 25.48 90 bottom
RC442  0_0402_5%  [R_0402]  77.61 113.55 90 top
RD1  0_0402_5%  [R_0402]  70.16 42.64 90 top
RD2  0_0402_5%  [R_0402]  69.21 42.64 90 top
RD3  0_0402_5%  [R_0402]  68.11 67.16 0 top
RD4  0_0402_5%  [R0402_0OHM]  70.48 44.86 90 top
RD5  0_0402_5%  [R0402_0OHM]  69.4 44.99 135 top
RD6  0_0402_5%  [R0402_0OHM]  69.22 65.74 180 top
RD7  470_0402_1%  [R_0402]  70.92 82.02 90 top
RD8  0_0402_5%  [R0402_0OHM]  70.04 82.9 180 top
RD9  2_0402_1%  [R_0402]  70.78 64.62 0 top
RD10  1K_0402_1%~D  [R_0402]  70.78 67.48 0 top
RD11  24.9_0402_1%  [R_0402]  71.7 62.72 180 top
RD12  1K_0402_1%~D  [R_0402]  71.7 66.53 180 top
RD13  0_0402_5%  [R_0402]  55.41 44.24 0 top
RD14  0_0402_5%  [R0402_0OHM]  55.41 43.22 0 top
RD15  0_0402_5%  [R_0402]  56.25 68.7 270 top
RD16  0_0402_5%  [R0402_0OHM]  56.33 45.19 180 top
RD17  0_0402_5%  [R_0402]  56.33 42.27 180 top
RD18  0_0402_5%  [R0402_0OHM]  56.25 66.86 270 top
RD19  2_0402_1%  [R_0402]  58.07 68.05 0 top
RD20  1K_0402_1%~D  [R_0402]  58.07 67.1 0 top
RD21  1K_0402_1%~D  [R_0402]  58.97 66.13 180 top
RD22  24.9_0402_1%  [R_0402]  58.07 69.85 0 top
RD23  240_0402_1%  [R_0402]  71.96 76.62 180 top
RD24  240_0402_1%  [R_0402]  58.75 77.13 180 top
RE1  100K_0402_1%  [R_0402]  31.45 91.11 270 top
RE2  0_0603_5%  [R_0603]  43.08 60.66 90 top
RE3  100K_0402_1%  [R_0402]  30.95 87.24 270 top
RE4  100K_0402_1%  [R_0402]  31.75 87.23 270 top
RE6  100K_0402_1%  [R_0402]  35.76 91.11 180 top
RE7  0_0603_5%  [R0603_0OHM]  30.06 66.29 270 top
RE8  4.7K_0402_5%  [R_0402]  39.37 63.76 180 top
RE9  4.7K_0402_5%  [R_0402]  40.22 63.76 0 top
RE10  2.2K_0402_5%  [R_0402]  41.15 62.22 270 top
RE11  2.2K_0402_5%  [R_0402]  42.04 62.22 270 top
RE12  1K_0402_5%  [R_0402]  73.24 37.83 270 top
RE13  10K_0402_5%  [R_0402]  53.51 72.69 0 top
RE14  100K_0402_5%  [R_0402]  53.58 67.67 0 top
RE15  100K_0402_5%  [R_0402]  48.95 86.26 90 top
RE16  10K_0402_5%  [R_0402]  50.85 86.26 90 top
RE17  100K_0402_5%  [R_0402]  38.44 62.48 0 top
RE18  100K_0402_5%  [R_0402]  29.51 86.7 180 top
RE19  1K_0402_5%  [R_0402]  43.42 89.2 90 top
RE20  10K_0402_5%  [R_0402]  36.95 87.09 90 top
RE21  100K_0402_5%  [R_0402]  33.97 66.05 270 top
RE23  43_0402_1%  [R_0402]  34.92 87.09 90 top
RE25  100K_0402_5%  [R_0402]  52.58 87.11 270 top
RE28  0_0402_5%  [R0402_0OHM]  32.34 83.37 270 top
RE29  1K_0402_5%  [R_0402]  32.09 73.67 180 top
RE30  2.2K_0402_5%  [R_0402]  31.85 88.9 180 top
RE31  2.2K_0402_5%  [R_0402]  31.85 88.01 180 top
RE32  100K_0402_5%  [R_0402]  32.09 72.75 180 top
RE37  0_0402_5%  [R0402_0OHM]  38.81 88.81 180 top
RE41  100K_0402_5%  [R_0402]  31.4 66 0 top
RE42  0_0402_5%  [R0402_0OHM]  53.51 74.84 0 top
RE43  100_0402_5%  [R_0402]  32.32 65.21 180 top
RE45  0_0402_5%  [R_0402]  33.09 68.95 270 top
RE46  10K_0402_1%  [R_0402]  49.39 63.85 90 top
RE47  0_0402_5%  [R_0402]  33.09 70.73 270 top
RE48  10K_0402_1%  [R_0402]  48.49 64.76 270 top
RE49  100K_0402_5%  [R_0402]  38.79 88 270 top
RE50  0_0603_5%  [R0603_0OHM]  33.78 89.64 90 top
RE51  300_0402_5%  [R_0402]  32.02 78.13 270 top
RE52  100K_0402_5%  [R_0402]  37.9 88 270 top
RE53  100K_0402_5%  [R_0402]  37.19 89.66 90 top
RE54  300_0402_5%  [R_0402]  32.09 74.46 180 top
RE55  10K_0402_5%  [R_0402]  38.98 95.36 0 top
RE56  100K_0402_5%  [R_0402]  38.98 94.59 0 top
RE57  10K_0402_5%  [R_0402]  38.98 93.07 0 top
RE58  10K_0402_5%  [R_0402]  38.98 92.31 0 top
RE59  49.9_0402_1%  [R_0402]  45.63 91.52 90 top
RE60  0_0402_5%  [R0402_0OHM]  33.91 83.37 270 top
RE61  0_0402_5%  [R0402_0OHM]  40.32 87.24 270 top
RE62  10K_0402_5%  [R_0402]  39.89 93.83 180 top
RE63  0_0402_5%  [R0402_0OHM]  33.12 83.37 270 top
RE65  0_0402_5%  [R_0402]  44.52 99.65 270 top
RE66  0_0603_5%  [R0603_0OHM]  55.44 78.72 270 top
RE67  33_0402_5%  [R_0402]  54.87 79.71 180 top
RE68  10K_0402_5%  [R_0402]  50.26 64.76 270 top
RE70  100K_0402_5%  [R_0402]  32.32 66.78 180 top
RE71  2.2K_0402_5%  [R_0402]  53.57 66.84 0 top
RE72  0_0603_5%  [R_0603]  47.88 90.78 270 top
RE81  0_0402_5%  [R_0402]  52.09 64.78 270 top
RE84  0_0201_5%  [R_0201]  91.8 36.38 0 bottom
RE85  0_0402_5%  [R_0402]  53.44 88.27 270 top
RE88  0_0402_5%  [R_0402]  29.73 73.44 270 top
RE89  0_0402_5%  [R_0402]  28.94 73.44 270 top
RE90  0_0402_5%  [R_0402]  37.83 85.68 180 top
RE91  0_0402_5%  [R_0402]  38.57 85.68 0 top
RE539  1K_0402_5%  [R_0402]  41.72 89.2 0 top
RE540  0_0402_5%  [R_0402]  92.36 38.24 0 bottom
RE541  100K_0402_5%  [R_0402]  53.37 63.81 90 top
RH1  100K_0402_1%_B25/50 4250K  [R_0402]  124.63 44.17 180 top
RI1  5.6_0402_1%  [R_0402]  16.98 93.64 180 top
RI2  5.6_0402_1%  [R_0402]  16.98 94.66 180 top
RI3  150_0402_5%  [R_0402]  14.92 94.48 270 top
RI4  5.6_0402_1%  [R_0402]  16.98 96.69 180 top
RI5  5.6_0402_1%  [R_0402]  16.98 95.67 180 top
RI6  150_0402_5%  [R_0402]  14.92 96.57 270 top
RI7  5.6_0402_1%  [R_0402]  16.98 89.7 180 top
RI8  5.6_0402_1%  [R_0402]  16.98 90.72 180 top
RI9  150_0402_5%  [R_0402]  14.92 90.54 270 top
RI10  5.6_0402_1%  [R_0402]  16.98 91.67 180 top
RI11  5.6_0402_1%  [R_0402]  16.98 92.69 180 top
RI12  150_0402_5%  [R_0402]  14.92 92.64 270 top
RI13  2.2K_0402_5%  [R_0402]  26.84 90.72 180 bottom
RI14  2.2K_0402_5%  [R_0402]  23.81 89.09 90 bottom
RI15  1M_0402_5%  [R_0402]  29.35 113.39 90 top
RI16  20K_0402_5%  [R_0402]  13.9 110.29 90 bottom
RL1  0_0603_5%  [R_0603]  21.59 85.64 90 top
RL2  2.49K_0402_1%  [R_0402]  19.74 79.76 0 top
RL3  1K_0402_5%  [R_0402]  24.6 87.22 270 top
RL4  15K_0402_5%  [R_0402]  24.62 88.01 180 top
RL5  0_0603_5%  [R0603_0OHM]  20.9 85.01 0 bottom
RL6  100K_0402_5%  [R_0402]  15.82 88.67 270 top
RL7  10K_0402_5%  [R_0402]  22.2 88.72 180 top
RL8  33_0402_5%  [R_0402]  19.04 82.29 0 top
RL9  33_0402_5%  [R_0402]  20 80.58 90 top
RL13  0_0402_5%  [R0402_0OHM]  29.74 79.55 90 top
RL14  75_0603_5%  [R_0603]  16.35 77.19 270 top
RL15  75_0603_5%  [R_0603]  17.62 77.19 270 top
RL17  0_0402_5%  [R_0402]  22.31 83.89 180 bottom
RL19  75_0603_5%  [R_0603]  16.35 77.19 270 bottom
RL20  75_0603_5%  [R_0603]  17.62 77.19 270 bottom
RL21  0_0402_5%  [R_0402]  22.17 83.04 180 bottom
RM1  0_0603_5%  [R_0603]  91.28 39.28 180 top
RM2  0_0603_5%  [R_0603]  92.24 29.12 0 top
RM3  20K_0402_5%  [R_0402]  79.99 39.75 270 top
RM12  20K_0402_5%  [R_0402]  85.57 39.74 270 top
RM13  20K_0402_5%  [R_0402]  76.23 33.01 270 top
RM14  10_0402_1%  [R_0402]  75.41 33.01 270 top
RM15  10_0402_1%  [R_0402]  79.22 39.74 270 top
RM16  10_0402_1%  [R_0402]  96.57 35.67 180 top
RM17  10_0402_1%  [R_0402]  96.57 33.89 180 top
RM18  10_0402_1%  [R_0402]  96.57 32.11 180 top
RM19  10_0402_1%  [R_0402]  96.58 37.35 180 top
RM20  10_0402_1%  [R_0402]  96.57 36.55 180 top
RM21  10_0402_1%  [R_0402]  96.57 34.78 180 top
RM22  10_0402_1%  [R_0402]  96.57 33 180 top
RM23  10_0402_1%  [R_0402]  96.57 31.22 180 top
RM24  10_0402_1%  [R_0402]  84.74 39.74 270 top
RM25  0_0402_5%  [R_0402]  82.96 39.74 270 top
RM27  10K_0402_5%  [R_0402]  82.14 38.83 90 top
RP1  100K_8P4R_5%  [RP_0804_8P4R]  179.18 67.29 225 top
RP2  100_8P4R_5%  [RP_0804_8P4R]  176.15 68.57 135 top
RP34  10K_8P4R_5%  [RP_0804_8P4R]  128.36 115.05 90 bottom
RPC1  10K_8P4R_5%  [RP_0804_8P4R]  142.42 48.69 0 bottom
RPC2  15_0804_8P4R_5%  [RP_0804_8P4R]  102.63 40.3 270 bottom
RPE1  10K_8P4R_5%  [RP_0804_8P4R]  36.79 63.91 270 top
RPE2  10K_8P4R_5%  [RP_0804_8P4R]  30.63 83.75 180 top
RPE3  100K_8P4R_5%  [RP_0804_8P4R]  44.64 60.74 90 top
RPE4  100K_8P4R_5%  [RP_0804_8P4R]  54.73 69.2 180 top
RPE5  100K_8P4R_5%  [RP_0804_8P4R]  47.79 87.8 270 top
RPE6  100K_8P4R_5%  [RP_0804_8P4R]  44.81 87.86 270 top
RPE7  10K_0804_8P4R_5%  [RP_0804_8P4R]  44.57 93.01 270 top
RPI1  470_8P4R_5%  [RP_0804_8P4R]  20.53 92.03 180 bottom
RPI2  470_8P4R_5%  [RP_0804_8P4R]  20.55 95.74 180 bottom
RPM1  20K_0804_8P4R_1%  [RP_0804_8P4R]  94.02 34.93 180 top
RPM2  20K_0804_8P4R_1%  [RP_0804_8P4R]  93.95 31.36 180 top
RS1  0_0402_5%  [R_0402]  186.17 33.46 270 top
RS2  10K_0402_5%  [R_0402]  23.82 36.47 0 bottom
RS3  100K_0402_5%  [R_0402]  195.61 33.38 90 top
RS4  100K_0402_5%  [R_0402]  184.96 35.11 270 top
RS5  10K_0402_5%  [R_0402]  175.71 45.11 180 top
RS6  0_0402_5%  [R_0402]  183.03 37.54 0 bottom
RS7  10K_0402_5%  [R_0402]  183.17 33.92 180 top
RT1  100K_0402_1%  [R_0402]  39.54 118.92 0 bottom
RT2  10K_0402_1%  [R_0402]  37.07 117.66 180 bottom
RT3  10K_0402_5%  [R_0402]  30.29 122.83 270 bottom
RT4  10K_0402_5%  [R_0402]  31.13 121.92 90 bottom
RT5  4.7K_0402_5%  [R_0402]  36.49 120.18 45 top
RT6  0_0402_5%  [R_0402]  30.17 116.72 270 top
RT8  10K_0402_5%  [R_0402]  35.96 120.79 225 top
RT11  1K_0402_5%  [R_0402]  20.75 119.36 0 top
RT12  1K_0402_5%  [R_0402]  21.67 120.12 180 top
RT13  20K_0402_5%  [R_0402]  21.67 120.88 180 top
RT14  1K_0402_5%  [R_0402]  24.37 125.64 180 bottom
RT15  1K_0402_5%  [R_0402]  22.2 123.22 180 top
RT16  20K_0402_5%  [R_0402]  22.2 123.98 180 top
RT17  1K_0402_5%  [R_0402]  16.87 128.79 0 bottom
RT18  1K_0402_5%  [R_0402]  21.07 126.34 270 top
RT19  20K_0402_5%  [R_0402]  20.31 126.34 270 top
RT20  1K_0402_5%  [R_0402]  16.87 127.97 0 bottom
RT21  1K_0402_5%  [R_0402]  18.77 126.34 270 top
RT22  20K_0402_5%  [R_0402]  19.53 126.34 270 top
RT23  1K_0402_5%  [R_0402]  24.7 123.03 180 bottom
RT24  1K_0402_5%  [R_0402]  22.2 121.7 180 top
RT25  20K_0402_5%  [R_0402]  22.2 122.46 180 top
RT26  1K_0402_5%  [R_0402]  13.83 125.52 0 bottom
RT27  1K_0402_5%  [R_0402]  15.88 123.83 0 top
RT28  20K_0402_5%  [R_0402]  15.88 124.62 0 top
RT29  1K_0402_5%  [R_0402]  13.83 124.69 0 bottom
RT30  1K_0402_5%  [R_0402]  17.46 121.28 0 top
RT31  20K_0402_5%  [R_0402]  17.46 120.52 0 top
RT32  100K_0402_5%  [R_0402]  23.38 128.31 180 top
RT33  100_1206_5%  [R_1206]  16.32 131.8 0 top
RT39  0_0402_5%  [R_0402]  25.8 130.81 180 bottom
RT40  0_0402_5%  [R_0402]  25.71 128.51 180 bottom
RT41  0_0402_5%  [R_0402-NPM]  33.35 130.22 180 bottom
RT42  0_0402_5%  [R_0402-NPM]  33.35 131.04 180 bottom
RT52  2.2K_0402_5%  [R_0402]  22.23 116.49 90 bottom
RT53  2.2K_0402_5%  [R_0402]  21.46 116.49 90 bottom
RT54  0_0402_5%  [R_0402]  16.11 128.81 270 bottom
RT55  0_0402_5%  [R_0402]  25.8 131.61 180 bottom
RT56  0_0402_5%  [R_0402]  25.8 132.44 180 bottom
RT57  0_0402_5%  [R_0402]  28.32 125.73 270 bottom
RT58  0_0402_5%  [R_0402]  27.43 125.73 270 bottom
RT59  200K_0402_1%  [R_0402]  30.23 118.39 90 top
RT62  10K_0402_5%  [R_0402]  37.88 132.43 0 top
RT63  100K_0402_5%  [R_0402]  34.53 128.05 0 top
RT64  75K_0402_1%  [R_0402]  35 125.28 270 top
RT65  45.3K_0402_1%  [R_0402]  35 123.6 270 top
RT66  4.7K_0402_5%  [R_0402]  45.43 107.38 0 top
RT67  4.7K_0402_5%  [R_0402]  48.31 107.98 90 top
RT68  4.7K_0402_5%  [R_0402]  45.43 106.49 0 top
RT69  4.7K_0402_5%  [R_0402]  49.1 107.98 90 top
RT70  4.7K_0402_5%  [R_0402]  45.43 105.6 0 top
RT71  4.7K_0402_5%  [R_0402]  47.57 105.53 0 top
RT72  4.7K_0402_5%  [R_0402]  45.43 104.71 0 top
RT73  4.7K_0402_5%  [R_0402]  47.57 104.74 0 top
RT74  4.7K_0402_5%  [R_0402]  45.28 110.62 0 top
RT75  4.7K_0402_5%  [R_0402]  45.28 109.48 0 top
RT76  4.7K_0402_5%  [R_0402]  48.83 109.63 90 top
RT77  4.7K_0402_5%  [R_0402]  43.94 112.65 90 top
RT78  4.7K_0402_5%  [R_0402]  43.17 112.65 90 top
RT79  4.7K_0402_5%  [R_0402]  45.28 111.41 0 top
RT80  4.7K_0402_5%  [R_0402]  44.76 112.47 0 top
RT81  4.7K_0402_5%  [R_0402]  44.76 113.25 0 top
RT82  4.99K_0402_1%  [R_0402]  31.3 112.54 90 top
RT83  4.7K_0402_5%  [R_0402]  43.94 115.22 270 top
RT84  4.7K_0402_5%  [R_0402]  43.17 115.22 270 top
RT93  100K_0402_5%  [R_0402]  29.77 104.52 90 top
RT94  100K_0402_5%  [R_0402]  30.58 104.53 0 top
RT97  100K_0402_5%  [R_0402]  33.12 104.53 180 top
RT98  100K_0402_5%  [R_0402]  28.61 104.52 90 top
RT99  1M_0402_1%  [R_0402]  37.97 102 0 top
RT100  1M_0402_1%  [R_0402]  34.46 101.96 0 top
RT101  0_0402_5%  [R_0402]  21.27 115.68 0 bottom
RT102  0_0201_5%  [R_0201]  30.62 111.87 90 top
RT103  0_0201_5%  [R_0201]  30.04 111.87 90 top
RT104  0_0201_5%  [R_0201]  41.04 113.72 270 bottom
RT105  0_0201_5%  [R_0201]  40.41 113.72 270 bottom
RT106  0_0201_5%  [R_0201]  39.26 113.72 270 bottom
RT107  0_0201_5%  [R_0201]  38.63 113.72 270 bottom
RT108  0_0201_5%  [R_0201]  37.44 113.72 270 bottom
RT109  0_0201_5%  [R_0201]  36.8 113.72 270 bottom
RT110  0_0201_5%  [R_0201]  35.71 113.72 270 bottom
RT111  0_0201_5%  [R_0201]  35.08 113.72 270 bottom
RT112  100K_0402_1%  [R_0402]  38.77 118.56 270 bottom
RT113  100K_0402_1%  [R_0402]  37.94 118.56 270 bottom
RT114  0_0402_5%  [R_0402]  23.02 115.77 270 bottom
RT115  4.7K_0402_5%  [R_0402]  33.18 112.97 90 top
RT116  100K_0402_5%  [R_0402]  31.07 106.73 0 top
RT117  100K_0402_5%  [R_0402]  31.07 105.93 0 top
RT118  0_0402_5%  [R_0402]  33.6 128.47 180 bottom
RT119  0_0402_5%  [R_0402]  33.6 129.29 180 bottom
RT120  0_0402_5%  [R_0402]  41.72 131.17 90 top
RT121  10K_0402_5%  [R_0402]  29.59 121.42 180 top
RU1  0_0402_5%  [R_0402-NPM]  33.57 51.96 90 top
RU2  0_0402_5%  [R_0402-NPM]  32.79 51.96 90 top
RU3  0_0402_5%  [R_0402]  21.96 59.16 0 top
RU4  0_0402_5%  [R_0402]  21.96 58.14 0 top
RU5  0_0402_5%  [R_0402]  21.96 57.32 0 top
RU6  0_0402_5%  [R_0402]  21.96 56.3 0 top
RU7  0_0402_5%  [R_0402-NPM]  32.15 39.41 180 bottom
RU8  0_0402_5%  [R_0402-NPM]  32.15 40.17 180 bottom
RU9  0_0402_5%  [R_0402]  17.73 34.38 90 top
RU10  0_0402_5%  [R_0402]  18.49 34.38 90 top
RU11  0_0402_5%  [R_0402]  19.75 34.38 90 top
RU12  0_0402_5%  [R_0402]  20.51 34.38 90 top
RU13  0_0402_5%  [R_0402-NPM]  210.89 32.99 90 top
RU14  0_0402_5%  [R_0402-NPM]  210.06 32.99 90 top
RU15  0_0402_5%  [R_0402-NPM]  207.77 32.99 90 top
RU16  0_0402_5%  [R_0402-NPM]  207.01 32.99 90 top
RU21  0_0402_5%  [R_0402]  33.91 45.14 270 top
RU22  0_0402_5%  [R_0402]  33.09 45.14 270 top
RU23  80.6K_0402_1%  [R_0402]  29.78 45.08 270 top
RU24  30K_0402_1%  [R_0402]  30.61 45.08 270 top
RU25  1M_0402_5%  [R_0402]  35.1 45.13 270 top
RU26  100K_0402_1%  [R_0402]  34.95 51.43 0 top
RV1  1.69K_0402_1%  [R_0402]  121.25 139.12 90 top
RV2  1K_0402_1%  [R_0402]  124.57 128.43 0 top
RV3  1K_0402_1%  [R_0402]  120.17 139.12 90 top
RV4  100K_0402_5%  [R_0402]  109.69 141.46 270 bottom
RV5  45.3K_0402_1%  [R_0402]  123.95 123.53 0 top
RV6  45.3K_0402_1%  [R_0402]  122.66 119.67 90 top
RV8  8.45K_0402_1%  [R_0402]  115.68 134.27 90 top
RV9  2K_0402_1%  [R_0402]  116.58 135.17 270 top
RV11  8.45K_0402_1%  [R_0402]  113.89 136.61 270 top
RV12  2K_0402_1%  [R_0402]  114.78 135.71 90 top
RV13  4.75K_0402_1%  [R_0402]  113.89 133.91 90 top
RV15  8.45K_0402_1%  [R_0402]  113.08 139.57 0 top
RV16  4.75K_0402_1%  [R_0402]  114.33 138.67 180 top
RV17  1K_0402_1%  [R_0402]  128.18 120.71 90 top
RV20  1M_0402_5%  [R_0402]  109.67 145.29 270 bottom
RV21  10K_0402_5%  [R_0402]  123.93 117.7 90 bottom
RV27  0_0603_5%  [R_0603]  111.51 129.36 0 top
RV28  8.45K_0402_1%  [R_0402]  112.81 134.81 270 top
RV29  10K_0402_5%  [R_0402]  118.14 139.68 270 top
RV30  0_0603_5%  [R_0603]  112.24 128.13 0 top
RV31  0_0603_5%  [R_0603]  120.29 143.27 0 top
RV32  40.2_0402_1%  [R_0402]  132.42 147.38 0 bottom
RV33  40.2_0402_1%  [R_0402]  131.43 146.36 180 bottom
RV34  100_0402_1%  [R_0402]  130.51 147.12 0 bottom
RV35  100_0402_1%  [R_0402]  134.64 147.38 0 bottom
RV36  49.9_0402_1%  [R_0402]  150.05 116.58 270 bottom
RV37  10_0402_1%  [R_0402]  149.29 116.58 270 bottom
RV38  5.1K_0402_1%  [R_0402]  148.53 116.58 270 bottom
RV39  120_0402_1%  [R_0402]  121.7 145.4 0 top
RV40  51.1_0402_1%  [R_0402]  129.71 119.1 90 top
RV41  51.1_0402_1%  [R_0402]  127.9 119.39 180 top
RV48  2.37K_0402_1%  [R_0402]  164.25 120.95 90 top
RV49  5.49K_0402_1%  [R_0402]  164.24 122.74 0 top
RV50  2.37K_0402_1%  [R_0402]  155.49 115.74 90 bottom
RV51  5.49K_0402_1%  [R_0402]  153.71 116.65 270 bottom
RV52  2.37K_0402_1%  [R_0402]  164.06 146.24 270 top
RV53  5.49K_0402_1%  [R_0402]  163.98 143.5 0 top
RV54  2.37K_0402_1%  [R_0402]  153.62 149.06 90 bottom
RV55  5.49K_0402_1%  [R_0402]  154.64 149.92 0 bottom
RV59  10K_0402_5%  [R_0402]  119.18 140.03 270 top
RV79  120_0402_1%  [R_0402]  154.64 149.96 270 top
RV81  4.7K_0402_5%  [R_0402]  120.99 119.36 270 bottom
RV82  4.7K_0402_5%  [R_0402]  121.8 119.34 270 bottom
RV83  16.2K_0402_1%  [R_0402]  120.17 119.36 270 bottom
RV84  10K_0402_5%  [R_0402]  108.96 127.11 180 bottom
RV85  120_0402_1%  [R_0402]  155.49 115.74 90 top
RV86  120_0402_1%  [R_0402]  154.6 115.74 90 top
RV87  10K_0402_5%  [R_0402]  108.94 128.01 180 bottom
RV88  10K_0402_5%  [R_0402]  108.02 128.91 0 bottom
RV89  10K_0402_5%  [R_0402]  110.74 127.11 180 bottom
RV116  1K_0402_1%  [R_0402]  155.09 132.45 0 top
RV117  1K_0402_1%  [R_0402]  155.09 132.45 0 bottom
RV118  1K_0402_1%  [R_0402]  164.24 123.62 0 top
RV119  1K_0402_1%  [R_0402]  164.24 123.62 0 bottom
RV120  121_0402_1%  [R_0402]  153.71 116.65 270 top
RV121  121_0402_1%  [R_0402]  152.82 116.65 270 bottom
RV123  121_0402_1%  [R_0402]  156.43 149.08 90 top
RV131  1K_0402_1%  [R_0402]  155.09 133.4 0 bottom
RV132  121_0402_1%  [R_0402]  157.27 149.03 180 bottom
RV133  1K_0402_1%  [R_0402]  163.98 142.55 0 bottom
RV134  1K_0402_1%  [R_0402]  155.09 133.4 0 top
RV135  1K_0402_1%  [R_0402]  163.98 142.55 0 top
RV151  10K_0402_5%  [R_0402]  127.27 118.56 90 bottom
RV152  10K_0402_5%  [R_0402]  125.81 119.39 270 bottom
RV153  0_0402_5%  [R_0402]  124.88 118.47 90 bottom
RV154  5.1K_0402_1%  [R_0402]  127.36 120.71 90 top
RV155  0_0402_5%  [R_0402]  110.74 130.1 180 bottom
RV156  0_0402_5%  [R_0402]  110.74 129.23 180 bottom
RV157  0_0402_5%  [R_0402]  110.74 128.33 180 bottom
RV158  0_0402_5%  [R_0402]  116.31 138.13 90 top
RV159  0_0402_5%  [R_0402]  117.21 138.13 90 top
RV162  4.7K_0402_5%  [R_0402]  108.85 138.49 0 bottom
RV163  4.7K_0402_5%  [R_0402]  109.76 139.39 180 bottom
RV260  4.7K_0402_5%  [R_0402]  129.85 117.45 0 bottom
RV364  0_0603_5%  [R_0603]  117.59 117.18 180 bottom
RV368  10K_0402_5%  [R_0402]  124.93 120.32 0 bottom
RV369  10K_0402_5%  [R_0402]  126.02 119.36 90 top
RV370  120_0402_1%  [R_0402]  155.53 149.96 270 top
RW3  0_0805_5%  [R_0805]  77.29 119.44 0 top
RW5  0_0805_5%  [R_0805]  77.44 116.3 90 top
RW6  0_0402_5%  [R_0402]  68.31 117.11 90 bottom
RW9  0_0402_5%  [R0402_0OHM]  110.05 50.94 180 bottom
RW10  0_0402_5%  [R0402_0OHM]  69.15 117.11 90 bottom
RW11  100K_0402_5%  [R_0402]  67.71 139.11 90 top
RW12  10K_0402_5%  [R_0402]  72.17 140.6 270 top
RW13  0_0402_5%  [R_0402]  44.97 101.01 90 top
RW14  0_0402_5%  [R_0402]  41.91 99.55 90 top
RW15  0_0402_5%  [R_0402]  75.51 133.74 90 top
RX1  33_0402_5%  [R_0402]  114.11 30.21 270 bottom
RX2  33_0402_5%  [R_0402]  118.14 36.53 270 bottom
RX3  33_0402_5%  [R_0402]  115.1 32.81 180 bottom
RX4  10K_0402_5%  [R_0402]  115.08 33.61 180 bottom
RX5  10K_0402_5%  [R_0402]  108.02 26.7 180 bottom
RX6  0_0402_5%  [R_0402]  114.98 30.96 180 bottom
RX7  0_0402_5%  [R_0402]  108.51 35.54 0 bottom
RX8  0_0402_5%  [R_0402]  105.3 32.04 90 bottom
RX9  0_0402_5%  [R_0402]  106.37 27.66 180 bottom
RX10  0_0402_5%  [R_0402]  106.18 33.1 90 bottom
RZ1  22.1K_0402_1%  [R_0402]  161.69 29.05 90 top
RZ2  0_0402_5%  [R_0402]  145.79 91.16 0 top
RZ3  49.9K_0402_1%  [R_0402]  159.58 29.94 90 top
RZ4  0_0603_5%  [R_0603]  158.94 35.41 90 top
RZ6  0_0402_5%  [R_0402]  137.71 115.11 180 bottom
RZ7  10K_0402_5%  [R_0402]  129.73 111.49 180 bottom
RZ8  10K_0402_5%  [R_0402]  129.48 108.56 180 bottom
RZ9  0_0805_5%  [R_0805]  81.97 115.98 0 top
RZ10  0_0805_5%  [R_0805]  85.11 114.43 90 top
RZ16  0_0402_5%  [R_0402]  86.27 109.71 90 top
RZ21  0_0402_5%  [R_0402]  78.42 114.46 0 top
SW1  TST71-N-220-T170-S017_2P  [SW_TST71-N-220-T170-S017_2P]  29.4 63.36 270 top
SW2  TST71-N-220-T170-S017_2P  [SW_TST71-N-220-T170-S017_2P]  29.4 63.36 270 bottom
SW3  MSS3N-Q-T-R_3P  [SW_MSS3N-Q-T-R_3P]  132.18 31.66 270 bottom
T45  PAD~D  [TPC12]  19.76 84.62 0 top
T47  PAD~D  [TPC12]  20.9 82.47 0 top
TL1  350UH_NS0013LF  [BOTH_NS0013LF_16P]  16.98 64.24 90 bottom
TL2  350UH_NS0013LF  [BOTH_NS0013LF_16P]  16.98 73.13 270 top
TP1  PAD  [TPC12]  132.25 76.63 0 top
TP2  PAD  [TPC12]  134.17 79.12 0 top
TP3  PAD  [TPC12]  110.82 83.19 180 bottom
TP4  PAD  [TPC12]  109.57 84.36 180 bottom
TP5  PAD  [TPC12]  119.59 81.03 0 top
TP6  PAD  [TPC12]  118.4 80.07 0 top
TP7  PAD  [TPC12]  141.61 91.89 180 bottom
TP8  PAD  [TPC12]  133.26 74.58 0 top
TP9  PAD  [TPC12]  133.59 73.35 0 top
TP10  PAD  [TPC12]  116.53 58.21 0 top
TP11  PAD  [TPC12]  111.45 59.11 180 bottom
TP12  PAD  [TPC12]  116.57 56.5 0 top
TP13  PAD  [TPC12]  120.14 54.03 0 top
TP14  PAD  [TPC12]  140.83 84.67 180 bottom
TP15  PAD  [TPC12]  139.16 81.95 180 bottom
TP16  PAD  [TPC12]  140.2 81.17 180 bottom
TP17  PAD  [TPC12]  138.49 80.79 180 bottom
TP18  PAD  [TPC12]  140.45 82.43 180 bottom
TP19  PAD  [TPC12]  111.87 93.78 180 bottom
TP20  PAD  [TPC12]  113.6 90.08 0 top
TP21  PAD  [TPC12]  112.45 89.11 0 top
TP22  PAD  [TPC12]  110.8 94.5 180 bottom
TP23  PAD  [TPC12]  120.33 55.39 0 top
TP24  PAD  [TPC12]  121.71 55.72 0 top
TP25  PAD  [TPC12]  116.62 52.64 0 top
TP26  PAD  [TPC12]  117.94 52.59 0 top
TP27  PAD  [TPC12]  110.96 50.62 180 bottom
TP28  PAD  [TPC12]  111.07 47.1 180 bottom
TP29  PAD  [TPC12]  112.35 46.95 180 bottom
TP30  PAD  [TPC12]  114.51 93.76 180 bottom
TP31  PAD  [TPC12]  113.2 93.55 180 bottom
TP32  PAD  [TPC12]  131.25 67.72 0 top
TP33  PAD  [TPC12]  121.22 68.21 0 top
TP38  PAD  [TPC12]  122.7 62.7 0 top
TP39  PAD  [TPC12]  121.12 62.45 0 top
TP40  PAD  [TPC12]  73.39 66.53 0 top
TP41  PAD  [TPC12]  82 66.2 0 top
TP42  PAD  [TPC12]  66.05 65.64 0 top
TP43  PAD  [TPC12]  57.18 67.16 0 top
TP44  PAD  [TPC12]  42.06 64.6 0 top
TP46  PAD  [TPC12]  200.57 61.58 180 bottom
TP50  PAD  [TPC12]  125.36 127.31 0 top
TP51  PAD  [TPC12]  126.73 127.29 0 top
TP52  PAD  [TPC12]  117.05 127.17 0 top
TP53  PAD  [TPC12]  119.68 127.86 0 top
TP54  PAD  [TPC12]  116.87 125.89 0 top
TP55  PAD  [TPC12]  116.65 128.39 0 top
TP56  PAD  [TPC12]  118.46 127.38 0 top
TP57  PAD  [TPC12]  118.27 124.6 0 top
TP58  PAD  [TPC12]  118.46 125.89 0 top
TP59  PAD  [TPC12]  118.75 122.65 0 top
TP60  PAD  [TPC12]  119.58 126.59 0 top
TP61  PAD  [TPC12]  119.57 125.24 0 top
TP62  PAD  [TPC12]  120.84 125.1 0 top
TP63  PAD  [TPC12]  117.33 119.62 180 bottom
TP64  PAD  [TPC12]  118.32 120.51 180 bottom
TP65  PAD  [TPC12]  122.09 125.51 0 top
TP66  PAD  [TPC12]  120.44 123.9 0 top
TP67  PAD  [TPC12]  121.07 120.4 180 bottom
TP68  PAD  [TPC12]  119.73 120.41 180 bottom
TP69  PAD  [TPC12]  123.86 120.63 180 bottom
TP70  PAD  [TPC12]  123.1 116.19 180 bottom
TP72  PAD  [TPC12]  112.92 126.63 0 top
TP73  PAD  [TPC12]  118.91 132.83 0 top
TP74  PAD  [TPC12]  101.74 49.28 0 top
TP76  PAD  [TPC12]  120.34 57.09 0 top
TP77  PAD  [TPC12]  119.48 58.91 0 top
TP79  PAD  [TPC12]  125.43 50.99 0 top
TP84  PAD  [TPC12]  15.71 120.2 0 bottom
TP85  PAD  [TPC12]  14.79 121.8 0 bottom
TP86  PAD  [TPC12]  123.12 47.84 0 top
TP87  PAD  [TPC12]  124.16 48.57 0 top
TP88  PAD  [TPC12]  124.77 47.57 180 bottom
TP89  PAD  [TPC12]  34.21 118.44 180 bottom
TP90  PAD  [TPC12]  122.49 121.6 0 top
TPC1  PAD  [TPC12]  133.33 93.38 0 top
TPC2  PAD  [TPC12]  127.83 92.87 0 top
TPC3  PAD  [TPC12]  138.82 83.32 0 top
TPC4  PAD  [TPC12]  138.08 92.47 0 top
TPC5  PAD  [TPC12]  135.76 93.89 0 top
TPC6  PAD  [TPC12]  136.2 83.04 0 top
TPC7  PAD  [TPC12]  131.89 53.53 0 top
TPC8  PAD  [TPC12]  107.29 37.92 180 bottom
TPC9  PAD  [TPC12]  109.76 44.48 0 top
TPC10  PAD  [TPC12]  140.53 89.58 0 top
TPC11  PAD  [TPC12]  138.77 94.64 180 bottom
TPC12  PAD  [TPC12]  139.67 89.38 180 bottom
TPC13  PAD  [TPC12]  141.93 91.33 0 top
TPC14  PAD  [TPC12]  134.61 91.98 0 top
TPC15  PAD  [TPC12]  137.13 94.64 180 bottom
TPC16  PAD  [TPC12]  136.24 93.66 180 bottom
TPC17  PAD  [TPC12]  137.96 93.65 180 bottom
TPC18  PAD  [TPC12]  128.13 92.67 180 bottom
TPC19  PAD  [TPC12]  128.3 94.14 180 bottom
TPC20  PAD  [TPC12]  134.39 93.65 180 bottom
TPC21  PAD  [TPC12]  132.59 93.39 180 bottom
TPC22  PAD  [TPC12]  135.28 94.56 180 bottom
TPC23  PAD  [TPC12]  134.23 95.35 180 bottom
TPC24  PAD  [TPC12]  131.57 92.62 180 bottom
TPC25  PAD  [TPC12]  133.31 94.47 180 bottom
TPC26  PAD  [TPC12]  132.03 94.62 180 bottom
TPC27  PAD  [TPC12]  133.48 92.62 180 bottom
TPC28  PAD  [TPC12]  129.52 92.69 180 bottom
TPC29  PAD  [TPC12]  129.57 94.83 180 bottom
TPC30  PAD  [TPC12]  134.61 84.43 0 top
TPC31  PAD  [TPC12]  138.71 83.13 180 bottom
TPC32  PAD  [TPC12]  99.98 39.17 180 bottom
TPC33  PAD  [TPC12]  125.52 93.59 0 top
TPS1  PAD  [TPC12]  138.1 50 0 top
TPS2  PAD  [TPC12]  119.62 52.56 0 top
TPS3  PAD  [TPC12]  117.75 59.08 0 top
TPS4  PAD  [TPC12]  159.62 27.72 180 top
TPS5  PAD  [TPC12]  111.06 58.45 0 top
TPS6  PAD  [TPC12]  120.26 59.94 0 top
TPS8  PAD  [TPC12]  28.89 64.45 0 top
TPS9  PAD  [TPC12]  223.78 65.16 0 top
TPS10  PAD  [TPC12]  118.09 57.49 0 top
TPS11  PAD  [TPC12]  119.2 56.36 0 top
U1  -  [SY6288C20AAC_SOT23-5]  210.41 48.18 180 bottom
U2  -  [NCT7718W_MSOP8]  181.08 62.85 225 bottom
U3  -  [SY6288C20AAC_SOT23-5]  211.91 34.96 270 top
U4  -  [SN74AHC1G08DCKR_SC70-5]  41.47 94.86 0 top
UA1  -  [ALC3246-CG_MQFN48_6X6]  29.79 11.05 180 top
UC1  SKL-U_BGA1356  [SKL-U_BGA_1356P-T]  136.55 49.99 270 bottom
UC2  -  [74AUP1G07GW_TSSOP5]  104.2 99.89 0 top
UC3  -  [W25Q128FVSIQ_SO8]  127.5 33.88 180 bottom
UC4  -  [SN74AHC1G08DCKR_SC70-5]  103.86 42.83 0 top
UC5  -  [SN74AHC1G08DCKR_SC70-5]  100.63 30.52 180 bottom
UC6  -  [74AUP1G07GW_TSSOP5]  146.06 90.35 270 bottom
UC7  -  [74AUP1G07GW_TSSOP5]  146.06 92.96 270 bottom
UC9  -  [SN74AHC1G08DCKR_SC70-5]  144.71 90.1 270 top
UE1  -  [MEC1416-NU-D0_VTQFP128_14X14]  37.35 67.78 90 top
UE2  -  [NL17SZ06DFT2G_SC70-5]  38.04 91.12 270 top
UL1  -  [RTL8106E-CG_QFN32_4X4]  22.8 80.19 0 top
